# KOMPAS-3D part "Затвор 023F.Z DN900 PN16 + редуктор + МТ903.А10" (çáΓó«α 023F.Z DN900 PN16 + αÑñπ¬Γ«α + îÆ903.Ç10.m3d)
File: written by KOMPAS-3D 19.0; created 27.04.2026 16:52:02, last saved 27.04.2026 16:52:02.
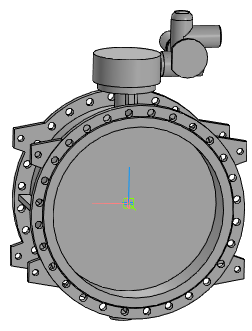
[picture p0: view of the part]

Document properties: Полное имя файла: ..\..\Затвор 023F.Z DN400-DN1600 + редуктор + МТ903\Затвор 023F.Z DN900 PN16 + редуктор + МТ903.А10.a3d

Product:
- Part/product: Затвор 023F.Z DN900 PN16 + редуктор + МТ903.А10
    Масса: 1134.77

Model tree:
1. Операция без истории:1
